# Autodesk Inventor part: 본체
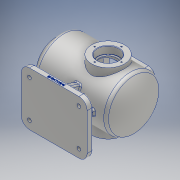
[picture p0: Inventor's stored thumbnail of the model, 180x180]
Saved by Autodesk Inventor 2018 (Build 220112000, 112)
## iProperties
Created: 2021-11
Part Number: 본체
Material: 알루미늄 6061
Document SubType Name: Modeling
Designer: na
Density: 2.7 g/cm^3
Appearance: 알루미늄 - 평지
Mass: 3541.09 g
Surface Area: 2403.18 cm^2
Volume: 1311.51 cm^3
Author: na
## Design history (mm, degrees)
sketch "스케치1"
  geometry: L1 (60, -65)-(-60, -65); L2 (-80, -45)-(-80, 45); L3 (-60, 65)-(60, 65); L4 (80, 45)-(80, -45); A1 r 20 centre (60, -45) between (60, -65) and (80, -45); A2 r 20 centre (-60, -45) between (-80, -45) and (-60, -65); A3 r 20 centre (-60, 45) between (-60, 65) and (-80, 45); A4 r 20 centre (60, 45) between (80, 45) and (60, 65); 6 further points
  constraints: 8 end point, 8 point on circle, 8 tangent, 6 point on line, 4 centre point, 2 midpoint, 2 parallel, 1 horizontal, 1 horizontal alignment, 1 perpendicular, 1 vertical alignment
  dimensions: "d0" = 160 distance of point (-80, 65) point (80, 65); "d1" = 130 distance of point (-80, -65) point (-80, 65); "d2" = 20 radius of A1; "d3" = 20 radius of A2; "d4" = 20 radius of A3; "d5" = 20 radius of A4
extrude "돌출1" new body sketch "스케치1" distance "d6" = 14; taper "d7" = 0 deg
sketch "스케치2"
  geometry: L1 (-80, 45)-(-80, -45) reference; L2 (-60, -65)-(60, -65) reference; L3 (80, -45)-(80, 45) reference; L4 (60, 65)-(-60, 65) reference; A1 r 20 centre (-60, -45) between (-80, -45) and (-60, -65) reference; A2 r 20 centre (60, -45) between (60, -65) and (80, -45) reference; A3 r 20 centre (60, 45) between (80, 45) and (60, 65) reference; A4 r 20 centre (-60, 45) between (-60, 65) and (-80, 45) reference; 1 further point
hole "구멍1" sketch "스케치2" at (-60, 45), (60, -45), (60, 45), (-60, -45) diameter "d8" = 9; stored, may be unused: countersink angle "d12" = 90 deg, drill point angle "d14" = 118 deg; dims "d9" = 6, "d10" = 18, "d11" = 2, "d13" = 8
sketch "스케치3"
  geometry: L1 (-110, 114)-(110, 114); L2 (-110, 114)-(-110, 146.5); L3 (-110, 146.5)-(-110, 161.5); L4 (-110, 161.5)-(-100, 161.5); L5 (-100, 161.5)-(-100, 179); L6 (-100, 179)-(75.993, 179); L7 (-110, 114)-(100, 114); L8 (-80, 0)-(-80, 14) reference; A1 r 100 centre (0, 114) between (100, 114) and (75.993, 179); 1 further point
  constraints: 14 end point, 2 horizontal, 2 perpendicular, 2 point on circle, 1 centre point, 1 midpoint, 1 point on line, 1 tangent, 1 vertical
  dimensions: "d15" = 114 distance from line of L1 point (0, 0); "d16" = 32.5 distance of L1.start L2.end; "d18" = 10 distance of L3.end L4.end; "d23" = 100 distance of L7.end A1.centre; "d25" = 65 distance from line of L7.end L6; "d26" = 130 diameter of L6 L1; "d27" = 95 diameter of L4 L1; "d35" = 30 distance between parallel lines of L8 L2
revolve "회전1" sketch "스케치3" stored, may be unused: angle "d28" = 90 deg
sketch "스케치4"
  geometry: L1 (-126.291, 114)-(138.957, 114); L2 (-100, 179)-(75.993, 179) reference; L3 (-85, 169)-(71.239, 169); L4 (-110, 146.5)-(-85, 146.5); L5 (-85, 146.5)-(-85, 169); L6 (-110, 66.5)-(-110, 161.5) reference; L7 (-110, 146.5)-(-110, 114); L8 (-110, 114)-(90, 114); A1 r 100 centre (0, 114) between (75.993, 49) and (75.993, 179) reference; A2 r 90 centre (0, 114) between (90, 114) and (71.239, 169); 1 further point
  constraints: 12 end point, 2 horizontal, 2 point on circle, 2 point on line, 1 centre point, 1 midpoint, 1 parallel, 1 perpendicular
  dimensions: "d29" = 114 distance from line of L1 point (0, 0); "d30" = 10 radial gap between concentric circles of A1 A2; "d31" = 10 distance between parallel lines of L3 L2; "d32" = 25 distance of L4.start L4.end; "d33" = 65 diameter of L4 L1
revolve "회전2" sketch "스케치4" stored, may be unused: angle "d34" = 90 deg
sketch "스케치6"
  geometry: L1 (58.485, 33.809)-(14, 50); L2 (58.485, -33.809)-(14, -50); L3 (14, 54)-(14, 36) reference; L4 (14, -36)-(14, -54) reference; L5 (14, 45)-(14, 65) reference; L6 (14, -65)-(14, -45) reference; L7 (14, 50)-(14, -50); L8 (12, -54)-(12, -36) reference; A1 r 65 centre (114, 0) between (58.485, 33.809) and (58.485, -33.809) reference; 1 further point
  constraints: 6 end point, 2 point on circle, 2 point on line, 1 parallel
  dimensions: "d36" = 50 vertical distance of point (0, 0) L1.end; "d37" = 100 distance of L2.end L1.end; "d38" = 110 deg angle of L5 L1; "d39" = 110 deg angle of L6 L2
extrude "돌출2" join sketch "스케치6" stored distance "d40" = 14; taper "d41" = 0 deg
sketch "스케치7"
  geometry: L1 (-45.794, 53.03)-(-60, 14); L2 (-69, 14)-(-51, 14) reference
  constraints: 2 end point
  dimensions: "d49" = 70 deg angle of L2 L1
feature "리브1" sketch "스케치7" dims "d50" = 1, "d51" = 14, "d52" = 0, "d53" = 0, "d54" = 1, "d55" = 1
node "작업 평면1"
sketch "스케치8"
  geometry: L1 (-110, 66.5)-(-110, 161.5) reference; L2 (80, 0)-(60, 0) reference; C1 r 40 at (17, 114)
  constraints: 1 centre point
  dimensions: "d57" = 80 diameter of C1; "d105" = 127 distance from line of C1.centre L1; "d106" = 114 distance from line of L2 C1.centre
extrude "돌출3" join sketch "스케치8" stored distance "d59" = 14; taper "d60" = 0 deg
sketch "스케치10"
  geometry: C1 r 40 at (0, 0) reference; 1 further point
hole "구멍2" sketch "스케치10" at (0, 0) diameter "d61" = 42; stored, may be unused: countersink angle "d65" = 90 deg, drill point angle "d67" = 118 deg; dims "d62" = 6, "d63" = 52, "d64" = 18, "d66" = 8
sketch "스케치11"
  geometry: C1 r 26 at (0, 0) reference; C2 r 40 at (0, 0) reference; 2 further points
  constraints: 1 vertical alignment
  dimensions: "d68" = 32.5 distance of C1.centre point (0, 32.5)
hole "구멍3" sketch "스케치11" at (0, 32.5) diameter "d69" = 3.242; stored, may be unused: countersink angle "d73" = 90 deg, drill point angle "d75" = 118 deg; dims "d70" = 11, "d71" = 52, "d72" = 18, "d74" = 13
node "작업 평면2"
sketch "스케치12"
  geometry: L1 (45, -30)-(-45, -30); L2 (-60, -15)-(-60, 15); L3 (-45, 30)-(45, 30); L4 (60, 15)-(60, -15); L5 (110, 47.5)-(110, -47.5) reference; A1 r 15 centre (45, -15) between (45, -30) and (60, -15); A2 r 15 centre (45, 15) between (60, 15) and (45, 30); A3 r 15 centre (-45, 15) between (-45, 30) and (-60, 15); A4 r 15 centre (-45, -15) between (-60, -15) and (-45, -30); 5 further points
  constraints: 8 end point, 8 point on circle, 8 point on line, 8 tangent, 4 centre point, 2 parallel, 1 horizontal, 1 perpendicular
  dimensions: "d81" = 120 distance of point (-60, 30) point (60, 30); "d82" = 60 distance of point (-60, -30) point (-60, 30); "d83" = 50 distance between parallel lines of L4 L5; "d84" = 30 distance from line of point (0, 0) L3; "d87" = 15 radius of A1; "d88" = 15 radius of A2; "d89" = 15 radius of A3; "d90" = 15 radius of A4
extrude "돌출4" join sketch "스케치12" stored distance "d85" = 14; taper "d86" = 0 deg
sketch "스케치13"
  geometry: L1 (-60, 15)-(-60, -15) reference; L2 (-45, 30)-(45, 30) reference; L3 (60, -15)-(60, 15) reference; L4 (45, -30)-(-45, -30) reference; L5 (45, 20)-(-45, 20); L6 (-50, 15)-(-50, -15); L7 (-45, -20)-(45, -20); L8 (50, -15)-(50, 15); 1 further point
  constraints: 8 end point, 7 parallel, 16 other
  dimensions: "d91" = 10 distance between parallel lines of L2 L5
extrude "돌출5" cut sketch "스케치13" stored distance "d92" = 14; taper "d93" = 0 deg
sketch "스케치14"
  geometry: L1 (50, 15)-(50, -15) reference; L2 (45, -20)-(-45, -20) reference; L3 (-50, -15)-(-50, 15) reference; L4 (-45, 20)-(45, 20) reference; L5 (-60, 15)-(-60, -15) reference; L6 (-45, -30)-(45, -30) reference; L7 (60, -15)-(60, 15) reference; L8 (45, 30)-(-45, 30) reference; A1 r 15 centre (-45, -15) between (-60, -15) and (-45, -30) reference; A2 r 15 centre (45, -15) between (45, -30) and (60, -15) reference; A3 r 15 centre (45, 15) between (60, 15) and (45, 30) reference; A4 r 15 centre (-45, 15) between (-45, 30) and (-60, 15) reference; 5 further points
  constraints: 2 horizontal alignment, 2 vertical alignment, 4 other
  dimensions: "d94" = 25 distance of point (0, 0) point (0, 25); "d95" = 55 distance of point (0, 0) point (-55, 0); "d96" = 55 distance of point (0, 0) point (55, 0); "d97" = 25 distance of point (0, -25) point (0, 0)
hole "구멍4" sketch "스케치14" at (0, 25), (-55, 0), (0, -25), (55, 0) diameter "d98" = 3.242; stored, may be unused: countersink angle "d102" = 90 deg, drill point angle "d104" = 118 deg; dims "d99" = 9, "d100" = 52, "d101" = 18, "d103" = 11
chamfer "모따기1" distance "d107" = 1; stored, may be unused: second distance "d108" = 2, angle "d109" = 45 deg
chamfer "모따기2" distance "d110" = 1; stored, may be unused: second distance "d111" = 2, angle "d112" = 45 deg
fillet "모깎기1" dims "d113" = 3
fillet "모깎기2" dims "d114" = 3
fillet "모깎기3" dims "d115" = 3
fillet "모깎기4" dims "d116" = 10
fillet "모깎기5" dims "d117" = 10
fillet "모깎기6" dims "d118" = 3
fillet "모깎기7" dims "d119" = 3
fillet "모깎기8" dims "d120" = 3
sketch "스케치16"
  geometry: L1 (0, 0)-(120, 0) reference; 3 further points
  constraints: 1 midpoint, 1 vertical alignment, 1 other
  dimensions: "d121" = 5 distance from line of L1 point (60, 5)
feature "엠보싱1" sketch "스케치16" dims "d81" = 120, "d122" = 0.5, "d123" = 0, "d135" = 0.3
sketch "스케치17"
  geometry: C1 r 47.5 at (0, 0) reference; 2 further points
  constraints: 1 vertical alignment
  dimensions: "d124" = 40 distance of C1.centre point (0, 40)
hole "구멍5" sketch "스케치17" at (0, 40) diameter "d125" = 3.242; stored, may be unused: countersink angle "d129" = 90 deg, drill point angle "d131" = 118 deg; dims "d126" = 11, "d127" = 52, "d128" = 18, "d130" = 13
fillet "모깎기9" dims "d135" = 0.3
node "솔리드1"
mirror "미러1"
pattern_circular "원형 패턴1" dims angle "d77" = 360 deg
mirror "미러2"
mirror "미러3"
pattern_circular "원형 패턴2" dims angle "d133" = 360 deg
node "투영된 루프1"
node "투영된 루프2"
node "투영된 루프3"
node "투영된 루프4"
other parameters: "d56" = 75, "d79" = 184
